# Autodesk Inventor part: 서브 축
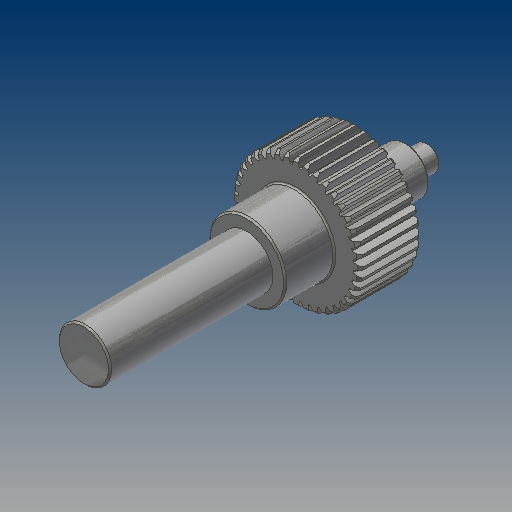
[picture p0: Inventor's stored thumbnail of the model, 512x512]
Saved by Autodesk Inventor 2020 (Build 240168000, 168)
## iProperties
CustomPartVersion: 1
Created: 2016-02
Part Number: 서브 축
Material: 강철, 연강
Document SubType Name: Modeling
Designer: mdu
Categories: <?xml version="1.0" encoding="UTF-16"?> <MemberInstance><Categories><FamilyTemplate><FamilyTemplateParameter ValueType="xs:double" Id="1" ObjectReferenceKey="da
Density: 7.86 g/cm^3
Appearance: 강철
Author: mdu
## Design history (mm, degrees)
sketch "Sketch1"
  geometry: C1 r 21 at (0, 0)
  constraints: 1 centre point
  dimensions: "d0" = 42 diameter of C1 (= da_da)
extrude "Extrusion1" new body sketch "Sketch1" distance "d1" = 20 (= da_b); taper "d2" = 0 deg
workplane "Work Plane2"
feature "피치 지름" dims "d4" = 10, "d5" = 0
workplane "Work Plane8"
workplane "Work Plane9"
chamfer "모따기1" distance "d49" = 1; stored, may be unused: second distance "d50" = 2, angle "d51" = 45 deg
sketch "스케치3"
  geometry: C1 r 12.5 at (0, 0); 1 further point
  constraints: 1 centre point, 1 coincident
  dimensions: "d52" = 25 diameter of C1
extrude "돌출2" join sketch "스케치3" distance "d53" = 16; taper "d54" = 0 deg
sketch "스케치4"
  geometry: C1 r 8.5 at (0, 0); 1 further point
  constraints: 1 centre point, 1 coincident
  dimensions: "d55" = 17 diameter of C1
extrude "돌출3" join sketch "스케치4" distance "d56" = 53; taper "d57" = 0 deg
sketch "스케치5"
  geometry: C1 r 7.5 at (0, 0); 1 further point
  constraints: 1 centre point, 1 coincident
  dimensions: "d62" = 15 diameter of C1
extrude "돌출4" join sketch "스케치5" distance "d63" = 16; taper "d64" = 0 deg
sketch "스케치6"
  geometry: C1 r 4 at (0, 0); 1 further point
  constraints: 1 centre point, 1 coincident
  dimensions: "d65" = 8 diameter of C1
extrude "돌출5" join sketch "스케치6" distance "d66" = 7; taper "d67" = 0 deg
chamfer "모따기2" distance "d58" = 0.5; stored, may be unused: second distance "d59" = 2, angle "d60" = 45 deg
fillet "모깎기1" dims "d61" = 0.5
feature "스퍼 기어" dims "da_b" = 20, "da_d" = 40, "da_aw" = 31, "da_da" = 42, "da_df" = 37.5, "da_dw" = 40, angle "da_beta" = 0 deg, "da_lefttooth" = 0, "da_righttooth" = 0
body "Solid1"
sketch "Sketch2"
  geometry: C1 r 21 at (0, 0) reference; C2 r 20 at (0, 0)
  constraints: 1 centre point, 1 coincident
  dimensions: "d3" = 40 diameter of C2 (= da_dw)
body "Srf1"
other parameters: "d16" = 31 (= da_aw), "d17" = 0, "d34" = 4.5 deg (computed from da_z), "d39" = 0, "d41" = 0, "d43" = 31 (= da_aw), "d46" = 31 (= da_aw), "d47" = 0, "d48" = 0
